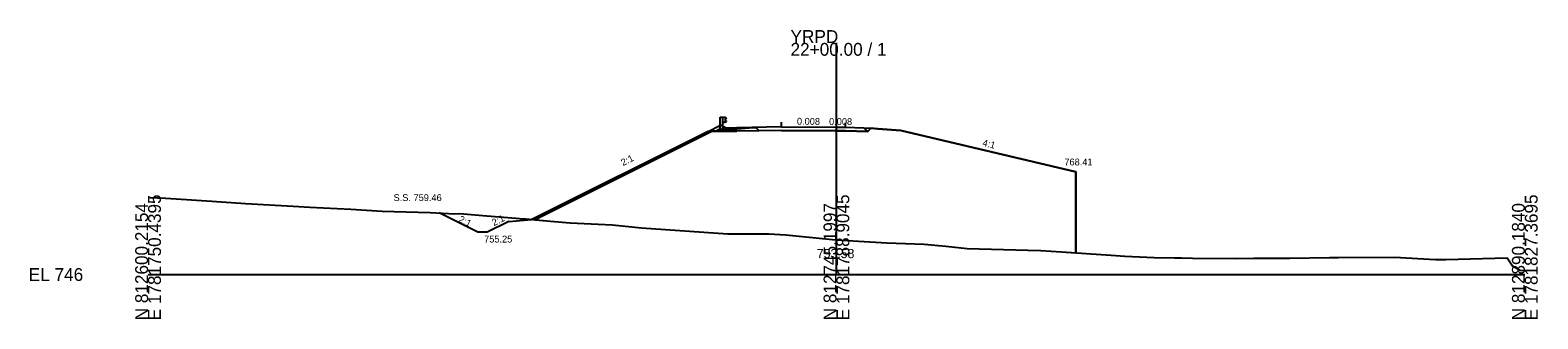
# Model space of a CAD drawing. Extents: x -26 to 1403, y -10 to 9544.
# Drawn here: x 974.3 to 1302.8, y 1990.3 to 2053.4 of the extents above; entities that cross this region are included whole.
import ezdxf

# ---------------------------------------------------------------- set-up
doc = ezdxf.new("R2010")
doc.units = 0
for name, color, linetype in [('Exist Cross Section Cell', 7, 'Continuous'), ('Exist XS Center Line Elevation Label', 7, 'Continuous'), ('Exist XS Ground Line', 7, 'Continuous'), ('Prop XS DDE', 7, 'Continuous'), ('Prop XS Ditch Standard Text', 7, 'Continuous'), ('Prop XS Dump Level', 7, 'Continuous'), ('Prop XS Earthwork Shape', 7, 'Continuous'), ('Prop XS EOT Tick Mark', 7, 'Continuous'), ('Prop XS Finish Grade', 7, 'Continuous'), ('Prop XS Finish Grade CurbGutter', 7, 'Continuous'), ('Prop XS Finish Grade Earthwork', 7, 'Continuous'), ('Prop XS Finish Grade Paved Shoulder', 7, 'Continuous'), ('Prop XS Finish Grade Pavement', 7, 'Continuous'), ('Prop XS Guardrail', 7, 'Continuous'), ('Prop XS Pvmt Edge Slope', 7, 'Continuous'), ('Prop XS SE Text', 7, 'Continuous'), ('Prop XS Side Slope Text', 7, 'Continuous'), ('Prop XS SS Elevation Text', 7, 'Continuous'), ('Prop XS Subgrade CurbGutter', 7, 'Continuous'), ('Prop XS Subgrade Earthwork', 7, 'Continuous')]:
    doc.layers.add(name, color=color, linetype=linetype)

msp = doc.modelspace()

# ---------------------------------------------------------------- linework, layer by layer
at = {"layer": 'Exist Cross Section Cell'}
for p, q in [((1150, 2000), (1150, 2050.57)), ((1000, 2000), (1150, 2000)), ((1150, 2000), (1300, 2000))]:
    msp.add_line(p, q, dxfattribs=at)
at = {"layer": 'Exist XS Ground Line'}
for p, q in [((1000, 2016.86), (1000.46, 2016.84)), ((1000.46, 2016.84), (1003.8, 2016.69)), ((1003.8, 2016.69), (1006.11, 2016.53)), ((1006.11, 2016.53), (1013.9, 2016.03)), ((1013.9, 2016.03), (1021.25, 2015.54)), ((1021.25, 2015.54), (1031.6, 2014.96)), ((1031.6, 2014.96), (1035.22, 2014.72)), ((1035.22, 2014.72), (1044.19, 2014.28)), ((1044.19, 2014.28), (1051.03, 2013.87)), ((1051.03, 2013.87), (1061.5, 2013.56)), ((1061.5, 2013.56), (1066.82, 2013.28)), ((1066.82, 2013.28), (1067.93, 2013.31)), ((1067.93, 2013.31), (1068.77, 2013.24)), ((1068.77, 2013.24), (1073.79, 2012.8)), ((1073.79, 2012.8), (1080.23, 2012.31)), ((1080.23, 2012.31), (1081.7, 2012.17)), ((1081.7, 2012.17), (1082.31, 2012.15)), ((1082.31, 2012.15), (1087.71, 2011.67)), ((1087.71, 2011.67), (1092.01, 2011.27)), ((1092.01, 2011.27), (1101.1, 2010.86)), ((1101.1, 2010.86), (1107.52, 2010.18)), ((1107.52, 2010.18), (1126.32, 2008.91)), ((1126.32, 2008.91), (1131.57, 2008.85)), ((1131.57, 2008.85), (1135.3, 2008.88)), ((1135.3, 2008.88), (1138.97, 2008.63)), ((1138.97, 2008.63), (1149.15, 2007.63)), ((1149.15, 2007.63), (1150, 2007.58)), ((1150, 2007.58), (1154.8, 2007.29)), ((1154.8, 2007.29), (1160.98, 2006.89)), ((1160.98, 2006.89), (1169.09, 2006.62)), ((1169.09, 2006.62), (1173.87, 2006.21)), ((1173.87, 2006.21), (1178.52, 2005.65)), ((1178.52, 2005.65), (1191.67, 2005.34)), ((1191.67, 2005.34), (1194.55, 2005.21)), ((1194.55, 2005.21), (1199.01, 2004.96)), ((1199.01, 2004.96), (1209.89, 2004.19)), ((1209.89, 2004.19), (1212.86, 2004.02)), ((1212.86, 2004.02), (1219.22, 2003.75)), ((1219.22, 2003.75), (1223.63, 2003.63)), ((1223.63, 2003.63), (1224.26, 2003.62)), ((1224.26, 2003.62), (1225.21, 2003.61)), ((1225.21, 2003.61), (1227.62, 2003.6)), ((1227.62, 2003.6), (1237.23, 2003.53)), ((1237.23, 2003.53), (1240.97, 2003.55)), ((1240.97, 2003.55), (1248.82, 2003.58)), ((1248.82, 2003.58), (1257.44, 2003.71)), ((1257.44, 2003.71), (1258.26, 2003.71)), ((1258.26, 2003.71), (1259.32, 2003.73)), ((1259.32, 2003.73), (1271.6, 2003.8)), ((1271.6, 2003.8), (1280.53, 2003.28)), ((1280.53, 2003.28), (1282.77, 2003.29)), ((1282.77, 2003.29), (1296.16, 2003.61)), ((1296.16, 2003.61), (1297.31, 2001.9)), ((1297.31, 2001.9), (1298.97, 2000.96)), ((1298.97, 2000.96), (1300, 2000.86))]:
    msp.add_line(p, q, dxfattribs=at)
at = {"layer": 'Prop XS DDE'}
for p, q in [((1071.88, 2009.25), (1063.46, 2013.46)), ((1078.61, 2011.61), (1073.88, 2009.25)), ((1078.61, 2011.61), (1083.61, 2012.04)), ((1073.88, 2009.25), (1071.88, 2009.25))]:
    msp.add_line(p, q, dxfattribs=at)
at = {"layer": 'Prop XS Dump Level'}
for p, q in [((1138, 2032.25), (1150, 2032.16)), ((1150, 2032.16), (1152, 2032.14))]:
    msp.add_line(p, q, dxfattribs=at)
at = {"layer": 'Prop XS Earthwork Shape'}
msp.add_lwpolyline([(1150, 2007.58), (1154.8, 2007.29), (1160.98, 2006.89), (1169.09, 2006.62), (1173.87, 2006.21), (1178.52, 2005.65), (1191.67, 2005.34), (1194.55, 2005.21), (1199.01, 2004.96), (1202.19, 2004.74), (1202.19, 2022.41), (1164, 2031.42), (1159, 2031.82), (1157.5, 2031.94), (1156.81, 2031.26), (1151.99, 2031.35), (1149.99, 2031.37), (1138, 2031.46), (1133.19, 2031.36), (1132.5, 2032.05), (1131, 2031.93), (1123, 2031.29), (1084.36, 2011.97), (1087.71, 2011.67), (1092.01, 2011.27), (1101.1, 2010.86), (1107.52, 2010.18), (1126.32, 2008.91), (1131.57, 2008.85), (1135.3, 2008.88), (1138.97, 2008.63), (1149.15, 2007.63)], close=True, dxfattribs=at)
at = {"layer": 'Prop XS EOT Tick Mark'}
for p, q in [((1138, 2032.25), (1138, 2033.25)), ((1152, 2032.14), (1152, 2033.14))]:
    msp.add_line(p, q, dxfattribs=at)
at = {"layer": 'Prop XS Finish Grade'}
for p, q in [((1122.07, 2031.26), (1124.73, 2032.59)), ((1125.31, 2032.3), (1124.73, 2032.59)), ((1156, 2032.06), (1157.5, 2031.94))]:
    msp.add_line(p, q, dxfattribs=at)
at = {"layer": 'Prop XS Finish Grade CurbGutter'}
for p, q in [((1126, 2031.96), (1125.31, 2032.3)), ((1128.33, 2032.06), (1126, 2031.96))]:
    msp.add_line(p, q, dxfattribs=at)
at = {"layer": 'Prop XS Finish Grade Earthwork'}
for p, q in [((1122.07, 2031.26), (1083.61, 2012.04)), ((1157.5, 2031.94), (1159, 2031.82)), ((1159, 2031.82), (1164, 2031.42)), ((1164, 2031.42), (1202.19, 2022.41)), ((1202.19, 2022.41), (1202.19, 2004.74))]:
    msp.add_line(p, q, dxfattribs=at)
at = {"layer": 'Prop XS Finish Grade Paved Shoulder'}
for p, q in [((1138, 2032.25), (1128.33, 2032.06)), ((1152, 2032.14), (1156, 2032.06))]:
    msp.add_line(p, q, dxfattribs=at)
at = {"layer": 'Prop XS Finish Grade Pavement'}
for p, q in [((1138, 2032.25), (1150, 2032.16)), ((1150, 2032.16), (1152, 2032.14))]:
    msp.add_line(p, q, dxfattribs=at)
at = {"layer": 'Prop XS Guardrail'}
for p, q in [((1124.68, 2034.36), (1125.18, 2034.36)), ((1124.68, 2031.86), (1124.68, 2034.36)), ((1125.18, 2034.36), (1125.68, 2034.36)), ((1125.18, 2034.36), (1125.18, 2031.86)), ((1125.68, 2034.36), (1125.97, 2034.16)), ((1125.97, 2034.04), (1125.68, 2033.84)), ((1125.68, 2033.84), (1125.68, 2033.74)), ((1125.68, 2033.74), (1125.97, 2033.54)), ((1125.97, 2034.16), (1126, 2034.1)), ((1126, 2034.1), (1125.97, 2034.04)), ((1125.68, 2033.22), (1125.18, 2033.22)), ((1125.97, 2033.42), (1125.68, 2033.22)), ((1125.97, 2033.54), (1126, 2033.48)), ((1126, 2033.48), (1125.97, 2033.42))]:
    msp.add_line(p, q, dxfattribs=at)
at = {"layer": 'Prop XS Pvmt Edge Slope'}
for p, q in [((1124.31, 2031.64), (1123.94, 2031.26)), ((1125.31, 2031.64), (1124.31, 2031.64)), ((1156, 2032.06), (1156.81, 2031.26))]:
    msp.add_line(p, q, dxfattribs=at)
at = {"layer": 'Prop XS Subgrade CurbGutter'}
for p, q in [((1125.31, 2031.64), (1125.31, 2032.3)), ((1128.33, 2031.64), (1125.31, 2031.64)), ((1128.33, 2032.06), (1128.33, 2031.64))]:
    msp.add_line(p, q, dxfattribs=at)
at = {"layer": 'Prop XS Subgrade Earthwork'}
for p, q in [((1123.94, 2031.26), (1122.07, 2031.26)), ((1128.33, 2031.26), (1123.94, 2031.26)), ((1138, 2031.46), (1128.33, 2031.27)), ((1128.33, 2031.27), (1128.33, 2031.26)), ((1138, 2031.46), (1149.99, 2031.37)), ((1149.99, 2031.37), (1151.99, 2031.35)), ((1151.99, 2031.35), (1156.81, 2031.26)), ((1156.81, 2031.26), (1157.5, 2031.94))]:
    msp.add_line(p, q, dxfattribs=at)

# ---------------------------------------------------------------- texts
at = {"layer": 'Exist Cross Section Cell'}
for s, p in [('YRPD', (1140, 2050.57)), ('22+00.00 / 1', (1140, 2047.77)), ('EL 746', (974, 1998.6))]:
    msp.add_text(s, height=2.8, dxfattribs=at).set_placement(p)
for s, p in [('E 1781750.4395', (1002.8, 1990)), ('E 1781788.9045', (1152.8, 1990)), ('E 1781827.3695', (1302.8, 1990)), ('N 812600.2154', (1000, 1990)), ('N 812745.1997', (1150, 1990)), ('N 812890.1840', (1300, 1990))]:
    msp.add_text(s, height=2.8, rotation=90, dxfattribs=at).set_placement(p)
at = {"layer": 'Exist XS Center Line Elevation Label'}
msp.add_text('753.58', height=2, dxfattribs=at).set_placement((1145.73, 2003.58))
at = {"layer": 'Prop XS Ditch Standard Text'}
for s, p in [('768.41', (1199.67, 2023.82)), ('755.25', (1073.23, 2006.99))]:
    msp.add_text(s, height=1.5, dxfattribs=at).set_placement(p)
at = {"layer": 'Prop XS Dump Level'}
for s, p in [('Case4', (1126, 2031.49)), ('Case2', (1128.33, 2032.02)), ('Case4', (1164, 2031.38))]:
    msp.add_text(s, height=0.04, dxfattribs=at).set_placement(p)
at = {"layer": 'Prop XS SE Text'}
for p in [(1141.39, 2032.72), (1148.39, 2032.67)]:
    msp.add_text('0.008', height=1.5, rotation=359.5613, dxfattribs=at).set_placement(p)
at = {"layer": 'Prop XS Side Slope Text'}
for s, rotation, p in [('4:1', 345.9638, (1181.72, 2028.12)), ('2:1', 26.5651, (1103.5, 2023.66)), ('2:1', 333.4349, (1067.51, 2011.59)), ('2:1', 26.5651, (1075.36, 2010.55))]:
    msp.add_text(s, height=1.5, rotation=rotation, dxfattribs=at).set_placement(p)
at = {"layer": 'Prop XS SS Elevation Text'}
msp.add_text('S.S. 759.46', height=1.5, dxfattribs=at).set_placement((1053.5, 2016.04))

doc.saveas('drawing.dxf')
